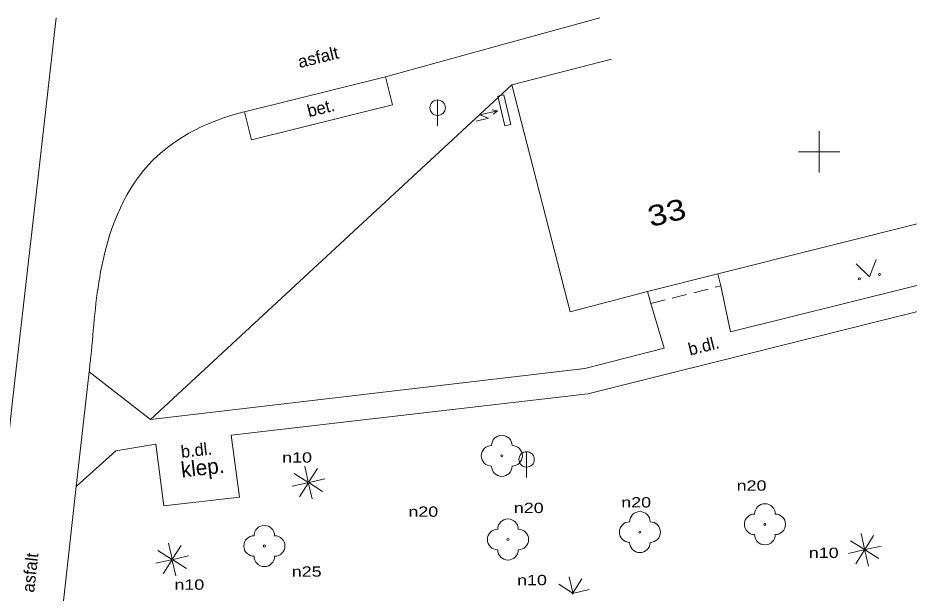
# Model space of a CAD drawing. Extents: x -670514 to -669423, y -1130798 to -1130123.
# Drawn here: x -669938.96 to -669895.62, y -1130621.47 to -1130593.48 of the extents above; entities that cross this region are included whole.
import ezdxf
from ezdxf.enums import TextEntityAlignment as Align

# ---------------------------------------------------------------- set-up
doc = ezdxf.new("R2010")
doc.units = 0
doc.header["$LTSCALE"] = 0.24
doc.linetypes.add('MEDIUM_DASHED', pattern=[4.5, 3, -1.5])
for name, color, linetype, lineweight in [('10', 7, 'Continuous', 13), ('14', 7, 'Continuous', 13), ('22', 7, 'Continuous', 13), ('24', 7, 'Continuous', 13), ('27', 7, 'Continuous', 13), ('36', 7, 'Continuous', 13), ('5', 7, 'Continuous', 13), ('61', 7, 'Continuous', 13)]:
    doc.layers.add(name, color=color, linetype=linetype, lineweight=lineweight)
for name, color, linetype in [('40', 7, 'Continuous'), ('42', 7, 'Continuous'), ('44', 7, 'Continuous'), ('47', 7, 'Continuous')]:
    doc.layers.add(name, color=color, linetype=linetype)

msp = doc.modelspace()

# ---------------------------------------------------------------- linework, layer by layer
at = {"layer": '10'}
for p, q in [((-669937.892, -1130600.497), (-669937.091, -1130593.481)), ((-669921.089, -1130596.349), (-669927.946, -1130598.051)), ((-669920.752, -1130597.708), (-669921.089, -1130596.349)), ((-669927.609, -1130599.41), (-669920.752, -1130597.708)), ((-669927.609, -1130599.41), (-669927.946, -1130598.051)), ((-669936.125, -1130616.271), (-669934.206, -1130614.54))]:
    msp.add_line(p, q, dxfattribs=at)
for points in [[(-669921.089, -1130596.349), (-669915.445, -1130594.797), (-669910.658, -1130593.481)], [(-669941.351, -1130641.441), (-669941.595, -1130634.042), (-669939.703, -1130616.745), (-669939.235, -1130612.262), (-669937.892, -1130600.497)], [(-669934.206, -1130614.54), (-669932.249, -1130614.211), (-669931.868, -1130617.218), (-669928.189, -1130616.795), (-669928.585, -1130613.788), (-669911.245, -1130611.765), (-669880.993, -1130604.213), (-669879.859, -1130608.986)], [(-669890.1, -1130605.226), (-669904.32, -1130608.757), (-669904.788, -1130606.523)], [(-669908.193, -1130607.377), (-669907.532, -1130609.543), (-669911.388, -1130610.535), (-669932.518, -1130613.023), (-669935.496, -1130610.702)], [(-669935.496, -1130610.702), (-669936.125, -1130616.271), (-669938.127, -1130634.286), (-669937.854, -1130640.741)]]:
    msp.add_lwpolyline(points, dxfattribs=at)
msp.add_spline([(-669927.946, -1130598.051), (-669928.311, -1130598.147), (-669932.612, -1130600.634), (-669934.937, -1130605.832), (-669935.415, -1130609.957), (-669935.496, -1130610.702)], degree=3, dxfattribs=at)
at = {"layer": '14'}
msp.add_line((-669914.948, -1130596.734), (-669932.518, -1130613.023), dxfattribs=at)
at = {"layer": '22'}
for p, q in [((-669924.84, -1130616.047), (-669925.012, -1130615.293)), ((-669924.866, -1130616.067), (-669925.522, -1130615.653)), ((-669924.398, -1130615.397), (-669924.812, -1130616.053)), ((-669925.626, -1130616.267), (-669924.872, -1130616.095)), ((-669924.852, -1130616.121), (-669925.266, -1130616.777)), ((-669924.824, -1130616.127), (-669924.652, -1130616.881)), ((-669924.142, -1130616.521), (-669924.798, -1130616.107)), ((-669924.792, -1130616.079), (-669924.038, -1130615.907)), ((-669897.794, -1130619.314), (-669897.966, -1130618.56)), ((-669897.352, -1130618.664), (-669897.766, -1130619.32)), ((-669931.467, -1130619.791), (-669931.639, -1130619.037)), ((-669931.025, -1130619.141), (-669931.439, -1130619.797)), ((-669897.82, -1130619.334), (-669898.476, -1130618.92)), ((-669897.746, -1130619.346), (-669896.992, -1130619.174)), ((-669931.493, -1130619.811), (-669932.149, -1130619.397)), ((-669931.419, -1130619.823), (-669930.665, -1130619.651)), ((-669898.58, -1130619.534), (-669897.826, -1130619.362)), ((-669897.806, -1130619.388), (-669898.22, -1130620.044)), ((-669897.778, -1130619.394), (-669897.606, -1130620.148)), ((-669897.096, -1130619.788), (-669897.752, -1130619.374)), ((-669932.253, -1130620.011), (-669931.499, -1130619.839)), ((-669931.479, -1130619.865), (-669931.893, -1130620.521)), ((-669931.451, -1130619.871), (-669931.279, -1130620.625)), ((-669930.769, -1130620.265), (-669931.425, -1130619.851)), ((-669911.984, -1130621.427), (-669912.156, -1130620.673)), ((-669911.542, -1130620.777), (-669911.956, -1130621.433)), ((-669912.01, -1130621.447), (-669912.666, -1130621.033)), ((-669911.936, -1130621.459), (-669911.182, -1130621.287))]:
    msp.add_line(p, q, dxfattribs=at)
for centre, radius in [((-669915.431, -1130614.786), 0.05), ((-669924.832, -1130616.087), 0.04), ((-669902.638, -1130618.117), 0.05), ((-669915.131, -1130618.855), 0.05), ((-669908.717, -1130618.496), 0.05), ((-669926.976, -1130619.173), 0.05), ((-669897.786, -1130619.354), 0.04), ((-669931.459, -1130619.831), 0.04), ((-669911.976, -1130621.467), 0.04)]:
    msp.add_circle(centre, radius, dxfattribs=at)
for centre, start, end in [((-669915.431, -1130614.286), 0, 180), ((-669915.931, -1130614.786), 90, 270), ((-669914.931, -1130614.786), 270, 90), ((-669915.431, -1130615.286), 180, 0), ((-669908.717, -1130617.996), 0, 180), ((-669902.638, -1130617.617), 0, 180), ((-669915.131, -1130618.355), 0, 180), ((-669903.138, -1130618.117), 90, 270), ((-669902.138, -1130618.117), 270, 90), ((-669926.976, -1130618.673), 0, 180), ((-669915.631, -1130618.855), 90, 270), ((-669914.631, -1130618.855), 270, 90), ((-669909.217, -1130618.496), 90, 270), ((-669908.217, -1130618.496), 270, 90), ((-669927.476, -1130619.173), 90, 270), ((-669926.476, -1130619.173), 270, 90), ((-669902.638, -1130618.617), 180, 0), ((-669908.717, -1130618.996), 180, 0), ((-669926.976, -1130619.673), 180, 0), ((-669915.131, -1130619.355), 180, 0)]:
    msp.add_arc(centre, 0.5, start, end, dxfattribs=at)
at = {"layer": '24'}
msp.add_line((-669915.626, -1130597.292), (-669915.291, -1130598.741), dxfattribs=at)
for points in [[(-669915.625, -1130597.292), (-669915.333, -1130597.224), (-669914.998, -1130598.673), (-669915.291, -1130598.74)], [(-669916.685, -1130598.501), (-669916.075, -1130598.36), (-669916.497, -1130598.201), (-669915.644, -1130598.004)], [(-669915.858, -1130598.166), (-669915.644, -1130598.004), (-669915.907, -1130597.952)]]:
    msp.add_lwpolyline(points, dxfattribs=at)
at = {"layer": '27'}
for p, q in [((-669918.552, -1130597.477), (-669918.552, -1130598.727)), ((-669914.226, -1130614.585), (-669914.226, -1130615.835))]:
    msp.add_line(p, q, dxfattribs=at)
for centre in [(-669918.5516, -1130597.8521), (-669914.2256, -1130614.9601)]:
    msp.add_circle(centre, 0.375, dxfattribs=at)
at = {"layer": '36'}
msp.add_lwpolyline([(-669898.206, -1130605.447), (-669897.557, -1130606.072), (-669897.23, -1130605.233)], dxfattribs=at)
for centre in [(-669898.0457, -1130606.1795), (-669897.0689, -1130605.9651)]:
    msp.add_circle(centre, 0.05, dxfattribs=at)
at = {"layer": '5'}
for p, q in [((-669910.105, -1130595.491), (-669914.948, -1130596.734)), ((-669914.948, -1130596.734), (-669912.112, -1130607.787)), ((-669904.935, -1130605.941), (-669873.428, -1130598.013)), ((-669908.34, -1130606.795), (-669904.935, -1130605.941)), ((-669904.935, -1130605.941), (-669904.788, -1130606.523)), ((-669908.34, -1130606.795), (-669912.112, -1130607.787)), ((-669908.34, -1130606.795), (-669908.193, -1130607.377))]:
    msp.add_line(p, q, dxfattribs=at)
at = {"layer": '5', "linetype": 'MEDIUM_DASHED'}
msp.add_line((-669908.193, -1130607.377), (-669904.788, -1130606.523), dxfattribs=at)
at = {"layer": '61'}
for p, q in [((-669900, -1130601), (-669900, -1130599)), ((-669901, -1130600), (-669899, -1130600))]:
    msp.add_line(p, q, dxfattribs=at)

# ---------------------------------------------------------------- texts
at = {"layer": '40', "width": 1.05}
msp.add_text('asfalt', height=0.6, rotation=13.94, dxfattribs=at).set_placement((-669924.2888, -1130595.6869), align=Align.CENTER)
at = {"layer": '40'}
for s, rotation, p in [('bet.', 13.94, (-669924.1563, -1130598.156)), ('b.dl.', 14.017, (-669905.5477, -1130609.7262)), ('b.dl.', 6.559, (-669930.2498, -1130614.8034)), ('asfalt', 83.659, (-669938.0653, -1130620.4986))]:
    msp.add_text(s, height=0.6, rotation=rotation, dxfattribs=at).set_placement(p, align=Align.CENTER)
at = {"layer": '42'}
msp.add_text('klep.', height=0.75, rotation=6.559, dxfattribs=at).set_placement((-669929.9388, -1130615.7229), align=Align.CENTER)
at = {"layer": '44', "width": 1.25}
msp.add_text('33', height=1, rotation=14.08, dxfattribs=at).set_placement((-669907.2931, -1130603.4395), align=Align.CENTER)
at = {"layer": '47', "width": 1.3}
for s, p in [('n10', (-669925.3845, -1130615.116)), ('n20', (-669903.2885, -1130616.481)), ('n20', (-669914.1215, -1130617.569)), ('n20', (-669908.8985, -1130617.297)), ('n20', (-669919.2485, -1130617.751)), ('n10', (-669899.7775, -1130619.753)), ('n25', (-669924.9175, -1130620.664)), ('n10', (-669930.6245, -1130621.299)), ('n10', (-669913.9645, -1130621.078))]:
    msp.add_text(s, height=0.5, dxfattribs=at).set_placement(p, align=Align.CENTER)

doc.saveas('drawing.dxf')
